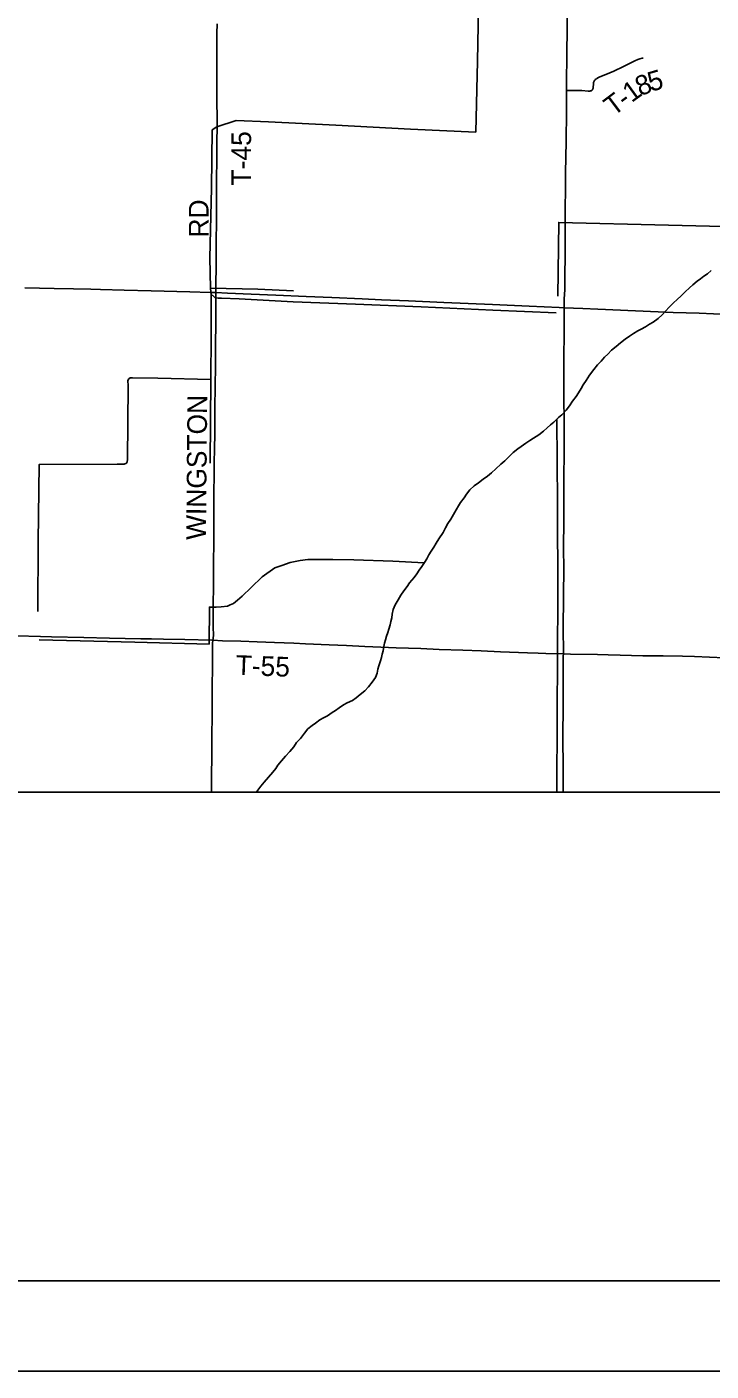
# Model space of a CAD drawing. Extents: x 0 to 680, y 0 to 834.
# Drawn here: x 166.4 to 242.2, y 0 to 148.8 of the extents above; entities that cross this region are included whole.
import ezdxf

# ---------------------------------------------------------------- set-up
doc = ezdxf.new("R2010")
doc.units = 0
for name, color, linetype in [('GM_X_County_Road', 7, 'Continuous'), ('GM_X_Interstate_Route', 7, 'Continuous'), ('GM_X_Major_River', 7, 'Continuous'), ('GM_X_Minor_River', 7, 'Continuous'), ('GM_X_State_Route', 7, 'Continuous'), ('GM_X_Township_Road', 7, 'Continuous'), ('GM_X_Township_Road_Text', 7, 'Continuous'), ('SH_Border', 7, 'Continuous'), ('SH_Cut_Line', 7, 'Continuous')]:
    doc.layers.add(name, color=color, linetype=linetype)

msp = doc.modelspace()

# ---------------------------------------------------------------- linework, layer by layer
at = {"layer": 'GM_X_County_Road'}
for points in [[(226.2, 141.45), (226.2, 141.71), (226.22, 143.21), (226.23, 145), (226.25, 146.31), (226.26, 147.99), (226.29, 150.13), (226.31, 153.48), (226.32, 154.55), (226.33, 155.03), (226.35, 155.82)], [(225.94, 117.4), (225.94, 117.43), (225.94, 117.67), (225.94, 118.03), (225.96, 118.62), (226.01, 119.7), (226.03, 120.89), (226.04, 123.76), (226.06, 126.86), (226.06, 128.77), (226.08, 130.68), (226.1, 132.59), (226.15, 136.05), (226.19, 139.39), (226.19, 140.59), (226.19, 141.3), (226.2, 141.45)], [(225.85, 79.1), (225.86, 79.36), (225.86, 79.48), (225.85, 82.22), (225.89, 89.03), (225.88, 90.82), (225.9, 94.4), (225.91, 96.67), (225.91, 98.81), (225.93, 101.68), (225.93, 104.19), (225.93, 105.62), (225.91, 107.17), (225.91, 109.08), (225.92, 112.18), (225.94, 114.81), (225.95, 116.36), (225.94, 117.4)], [(225.83, 64.07), (225.84, 66.35), (225.81, 70.53), (225.82, 73.27), (225.82, 75.06), (225.83, 76.5), (225.85, 79.1)]]:
    msp.add_lwpolyline(points, dxfattribs=at)
at = {"layer": 'GM_X_Interstate_Route'}
msp.add_lwpolyline([(44.69, 394.07), (374.69, 394.07), (374.69, 64.07), (44.69, 64.07)], close=True, dxfattribs=at)
at = {"layer": 'GM_X_Major_River'}
for points in [[(242.24, 121.79), (241.8, 121.43), (241.42, 121.15), (241.06, 120.88), (240.66, 120.62), (240.21, 120.2), (239.82, 119.86), (239.35, 119.44), (238.91, 118.99), (238.44, 118.57), (238.05, 118.22), (237.55, 117.71), (237.22, 117.32), (236.81, 116.88), (236.34, 116.47), (235.81, 116.09), (235.41, 115.85), (234.95, 115.57), (234.47, 115.3), (234.09, 115.11), (233.63, 114.83), (233.19, 114.51), (232.71, 114.19), (232.19, 113.79), (231.71, 113.38), (231.17, 112.96), (230.78, 112.54), (230.41, 112.19), (230.03, 111.76), (229.64, 111.36), (229.24, 110.85), (228.76, 110.22), (228.38, 109.63), (228.06, 109.13), (227.84, 108.74), (227.52, 108.24), (227.27, 107.85), (226.87, 107.32), (226.54, 106.82), (226.18, 106.35), (225.67, 105.83), (225.31, 105.51), (224.8, 105.01), (224.43, 104.71), (224.07, 104.39), (223.66, 104.02), (223.12, 103.59), (222.55, 103.25), (222.14, 102.98), (221.69, 102.69), (221.18, 102.31), (220.8, 102.05), (220.31, 101.67), (219.88, 101.25), (219.39, 100.74), (218.94, 100.36), (218.37, 99.85), (217.89, 99.42), (217.44, 99.04), (216.98, 98.69), (216.46, 98.31), (215.99, 97.95), (215.48, 97.51), (215.11, 97.05), (214.86, 96.62), (214.47, 96.13), (214.24, 95.75), (213.97, 95.3), (213.68, 94.79)], [(213.68, 94.79), (213.4, 94.29), (213.06, 93.78), (212.79, 93.3), (212.54, 92.81), (212.05, 92.11), (211.76, 91.63), (211.5, 91.18), (211.23, 90.75), (210.97, 90.32), (210.74, 89.87), (210.47, 89.49), (210.19, 89.02), (209.9, 88.63), (209.61, 88.22), (209.32, 87.83), (208.82, 87.23), (208.57, 86.81), (208.2, 86.34), (207.87, 85.85), (207.55, 85.35), (207.24, 84.8), (206.99, 84.27), (206.9, 83.76), (206.86, 83.37), (206.75, 82.96), (206.69, 82.58), (206.53, 82.12), (206.41, 81.75), (206.27, 81.33), (206.16, 80.94), (206.06, 80.56), (205.99, 80.18), (205.9, 79.7), (205.79, 79.32), (205.72, 78.95), (205.6, 78.59), (205.43, 78.05), (205.32, 77.66), (205.23, 77.25), (205.06, 76.77), (204.69, 76.23), (204.28, 75.73), (203.86, 75.27), (203.36, 74.89), (202.9, 74.5), (202.52, 74.22), (201.93, 73.96), (201.52, 73.74), (201.03, 73.39), (200.62, 73.12), (200.24, 72.87), (199.73, 72.52), (199.29, 72.29), (198.9, 72.06), (198.4, 71.7), (198.04, 71.46), (197.57, 71.07), (197.2, 70.58), (196.76, 70.01), (196.31, 69.57), (196.02, 69.08), (195.55, 68.55), (195.1, 68.06), (194.63, 67.53), (194.23, 67.04), (194.01, 66.68), (193.68, 66.28), (193.21, 65.73), (192.73, 65.19), (192.35, 64.74), (192.01, 64.29), (191.88, 64.07)]]:
    msp.add_lwpolyline(points, dxfattribs=at)
at = {"layer": 'GM_X_Minor_River'}
for points in [[(216.53, 175.71), (216.55, 167.73), (216.62, 160.67), (216.49, 152.88), (216.33, 144.96), (216.15, 137.1), (208.91, 137.43), (200.65, 137.89), (193.21, 138.23), (189.62, 138.4), (187.49, 137.69), (186.95, 137.35), (186.88, 130.9), (186.71, 123.18), (186.76, 119.84), (186.84, 119.08), (186.84, 114.6), (186.8, 109.72), (186.74, 100.48)], [(249.63, 126.5), (225.34, 127.12), (225.25, 118.96)], [(186.76, 119.84), (192.03, 119.71), (195.98, 119.54)], [(186.84, 119.08), (187.05, 119.01), (187.26, 118.82), (187.64, 118.73), (188.01, 118.73), (189.96, 118.65), (195.93, 118.34), (202.85, 118.06), (210.09, 117.77), (218.03, 117.42), (225.05, 117.09)], [(186.8, 109.72), (180.93, 109.86), (178.15, 109.93), (177.88, 109.9), (177.75, 109.79), (177.63, 109.61), (177.66, 109.03), (177.59, 100.87), (177.56, 100.63), (177.46, 100.47), (177.2, 100.36), (176.44, 100.35), (167.79, 100.32), (167.7, 91.81), (167.65, 84.04)], [(225.12, 64.07), (225.17, 72.55), (225.23, 85.84), (225.22, 96.05), (225.13, 105.33)], [(210.44, 89.44), (206.96, 89.61), (202.65, 89.76), (200.32, 89.82), (198.19, 89.83), (197.54, 89.82), (196.72, 89.69), (195.61, 89.47), (194.66, 89.16), (193.89, 88.88), (192.5, 87.9), (191.29, 86.73), (190.3, 85.77), (189.76, 85.32), (189.33, 84.95), (188.97, 84.78), (188.66, 84.66), (187.94, 84.56), (187.39, 84.55), (186.65, 84.55), (186.62, 80.45), (178.39, 80.68), (167.82, 80.92)]]:
    msp.add_lwpolyline(points, dxfattribs=at)
at = {"layer": 'GM_X_State_Route'}
msp.add_lwpolyline([(166.23, 119.89), (169.45, 119.81), (171.6, 119.75), (173.51, 119.71), (174.58, 119.68), (177.21, 119.61), (180.19, 119.54), (184.49, 119.44), (186.75, 119.37), (187.37, 119.35), (188.66, 119.3), (191.29, 119.19), (194.03, 119.06), (197.37, 118.92), (200.23, 118.79), (203.57, 118.65), (205.71, 118.55), (208.69, 118.43), (212.63, 118.25), (217.99, 118.02), (222.05, 117.84), (225.39, 117.69), (225.94, 117.67), (228.01, 117.58), (229.68, 117.53), (233.85, 117.34), (238.03, 117.16), (240.89, 117.06), (245.66, 116.85)], dxfattribs=at)
at = {"layer": 'GM_X_Township_Road'}
for points in [[(187.37, 119.35), (187.37, 119.48), (187.4, 123.06), (187.41, 124.85), (187.43, 127.36), (187.43, 129.39), (187.45, 131.89), (187.46, 134.04), (187.47, 135.12), (187.49, 136.31), (187.5, 137.38), (187.5, 138.94), (187.49, 140.25), (187.46, 142.16), (187.46, 143.59), (187.47, 144.54), (187.47, 146.22), (187.47, 147.05), (187.49, 148.01), (187.51, 149.08)], [(226.2, 141.71), (226.37, 141.72), (226.84, 141.72), (227.08, 141.72), (227.91, 141.7), (228.62, 141.65), (228.75, 141.65), (228.8, 141.65), (228.86, 141.66), (228.92, 141.67), (228.97, 141.69), (229, 141.72), (229.03, 141.74), (229.06, 141.77), (229.08, 141.8), (229.1, 141.83), (229.12, 141.89), (229.14, 141.94), (229.15, 142), (229.19, 142.48), (229.2, 142.54), (229.21, 142.6), (229.23, 142.66), (229.25, 142.71), (229.28, 142.76), (229.31, 142.81), (229.35, 142.86), (229.39, 142.9), (229.43, 142.95), (229.48, 142.98), (229.53, 143.02), (229.57, 143.05), (229.62, 143.08), (229.68, 143.11), (229.89, 143.21), (230.56, 143.48), (231.43, 143.86), (232.5, 144.38), (233.46, 144.85), (233.78, 145), (234.11, 145.14), (234.34, 145.21), (234.57, 145.27), (234.68, 145.3)], [(187.05, 80.89), (187.08, 81.05), (187.1, 81.53), (187.09, 82.24), (187.09, 83.2), (187.09, 85.11), (187.11, 86.54), (187.11, 88.81), (187.12, 90.12), (187.13, 91.07), (187.13, 92.74), (187.14, 95.73), (187.15, 97.4), (187.17, 98.95), (187.2, 100.38), (187.23, 102.17), (187.24, 103.6), (187.26, 106.11), (187.3, 109.45), (187.32, 110.77), (187.33, 111.84), (187.34, 113.87), (187.35, 115.66), (187.36, 116.97), (187.37, 119.35)], [(148.35, 81.83), (149.58, 81.8), (154, 81.69), (157.58, 81.58), (159.61, 81.52), (161.28, 81.48), (163.9, 81.4), (165.33, 81.36), (167.96, 81.3), (169.15, 81.26), (172.73, 81.19), (175.59, 81.12), (179.06, 81.04), (180.25, 81.02), (181.56, 81), (183.95, 80.96), (186.93, 80.89), (187.05, 80.89)], [(186.9, 64.07), (186.93, 69.84), (186.95, 72.94), (186.96, 75.57), (186.98, 78.08), (186.99, 79.87), (187.01, 80.58), (187.04, 80.81), (187.05, 80.89)], [(187.05, 80.89), (188.12, 80.83), (190.15, 80.76), (191.94, 80.69), (193.85, 80.62), (196, 80.55), (197.31, 80.48), (199.93, 80.37), (201.84, 80.3), (203.86, 80.2), (205.65, 80.12), (207.32, 80.05), (210.07, 79.95), (212.09, 79.86), (214.72, 79.77), (216.74, 79.69), (218.89, 79.6), (221.87, 79.5), (223.07, 79.45), (223.9, 79.42), (225.86, 79.36)], [(225.86, 79.36), (226.64, 79.34), (229.63, 79.29), (230.82, 79.26), (232.13, 79.22), (234.64, 79.17), (236.91, 79.14), (239.05, 79.1), (240.37, 79.06), (243.71, 78.94), (248.72, 78.74), (251.7, 78.61), (253.25, 78.52), (254.68, 78.43), (256.94, 78.31), (258.37, 78.23), (260.87, 78.09), (263.26, 77.94), (264.23, 77.9)]]:
    msp.add_lwpolyline(points, dxfattribs=at)
at = {"layer": 'SH_Border'}
msp.add_lwpolyline([(30, 430), (670, 430), (670, 10), (30, 10)], close=True, dxfattribs=at)
at = {"layer": 'SH_Cut_Line'}
msp.add_lwpolyline([(0, 0), (680, 0), (680, 440), (0, 440)], close=True, dxfattribs=at)

# ---------------------------------------------------------------- texts
at = {"layer": 'GM_X_Township_Road_Text'}
for s, height, rotation, p in [('8', 2.18, 23.312, (234.39, 141.04)), ('5', 2.18, 16.147, (235.55, 141.55)), ('T', 2.18, 37.0285, (231.4, 138.8)), ('1', 2.18, 35.9509, (233.41, 140.31)), ('-', 2.18, 36.8636, (232.7, 139.78)), ('T-45', 2.182, 90, (191.27, 131.2)), ('RD', 2.182, 90, (186.56, 125.44)), ('WINGSTON', 2.182, 89.4861, (186.27, 91.97)), ('T-55', 2.182, 357.9038, (189.54, 77.05))]:
    msp.add_text(s, height=height, rotation=rotation, dxfattribs=at).set_placement(p)

doc.saveas('drawing.dxf')
